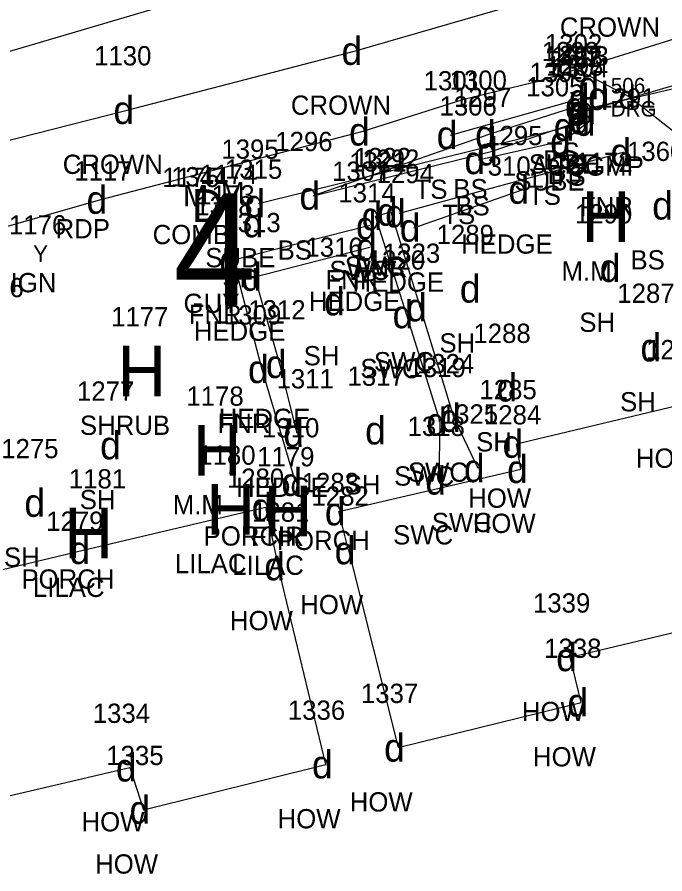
# Model space of a CAD drawing. Extents: x 461160 to 461373, y 202903 to 203086.
# Drawn here: x 461256.86 to 461282.42, y 202914.93 to 202948.72 of the extents above; entities that cross this region are included whole.
import ezdxf

# ---------------------------------------------------------------- set-up
doc = ezdxf.new("R2010")
doc.units = 0
for name, color, linetype in [('Level 11', 7, 'Continuous'), ('Level 12', 7, 'Continuous'), ('Level 13', 7, 'Continuous'), ('Level 14', 7, 'Continuous'), ('Level 15', 7, 'Continuous'), ('Level 43', 7, 'Continuous'), ('Level 46', 7, 'Continuous'), ('Level 47', 7, 'Continuous'), ('Level 48', 7, 'Continuous'), ('Level 49', 7, 'Continuous'), ('Level 59', 7, 'Continuous')]:
    doc.layers.add(name, color=color, linetype=linetype)

msp = doc.modelspace()

# ---------------------------------------------------------------- linework, layer by layer
at = {"layer": 'Level 11'}
msp.add_line((461277.244, 202946.143), (461284.854, 202948.511), dxfattribs=at)
for points in [[(461266.295, 202950.239), (461255.843, 202947.153), (461244.186, 202944.178), (461233.496, 202941.961), (461227.074, 202940.327)], [(461278.937, 202946.67), (461281.047, 202945.559), (461284.301, 202943.008)], [(461277.244, 202946.143), (461274.435, 202945.462), (461270.507, 202944.203)], [(461270.507, 202944.203), (461260.148, 202941.513), (461250.261, 202938.68), (461245.353, 202937.463), (461235.083, 202934.632), (461230.09, 202933.632), (461221.765, 202932.249), (461216.144, 202929.568), (461212.35, 202928.516)]]:
    msp.add_lwpolyline(points, dxfattribs=at)
at = {"layer": 'Level 12'}
for points in [[(461280.82, 202943.388), (461271.934, 202940.975)], [(461273.514, 202930.439), (461273.554, 202932.759), (461272.224, 202936.998), (461271.001, 202940.867), (461271.608, 202941.039), (461272.758, 202937.267), (461274.098, 202932.911), (461275.041, 202930.926)], [(461270.78, 202940.5), (461265.385, 202939.135), (461266.52, 202934.835), (461267.835, 202930.384)]]:
    msp.add_lwpolyline(points, dxfattribs=at)
at = {"layer": 'Level 13'}
for points in [[(461269.939, 202927.688), (461269.552, 202929.221), (461276.743, 202930.893), (461276.564, 202931.887), (461283.181, 202933.463)], [(461278.681, 202923.472), (461285.239, 202925.038), (461283.181, 202933.463)], [(461252.754, 202926.088), (461259.473, 202927.696), (461266.663, 202929.394), (461267.163, 202927.056)], [(461269.939, 202927.688), (461271.89, 202919.907), (461279.12, 202921.685), (461278.681, 202923.472)], [(461252.754, 202926.088), (461254.839, 202917.613), (461261.308, 202919.121), (461261.843, 202917.458), (461269.045, 202919.243), (461267.163, 202927.056)]]:
    msp.add_lwpolyline(points, dxfattribs=at)
at = {"layer": 'Level 14'}
for points in [[(461272.508, 202940.411), (461276.792, 202941.908)], [(461267.913, 202932.314), (461267.227, 202935.033), (461266.245, 202938.474), (461270.784, 202939.649)]]:
    msp.add_lwpolyline(points, dxfattribs=at)
at = {"layer": 'Level 15'}
msp.add_lwpolyline([(461266.383, 202941.371), (461278.58, 202944.397), (461279.146, 202945.068), (461287.08, 202946.903), (461292.543, 202942.281), (461300.755, 202937.586), (461303.654, 202934.874)], dxfattribs=at)
at = {"layer": 'Level 48'}
for points in [[(461211.555, 202934.121), (461222.234, 202936.16), (461232.093, 202938.078), (461241.693, 202939.978), (461251.734, 202942.643), (461261.209, 202945.054), (461270.211, 202947.385), (461280.824, 202950.466), (461289.045, 202954.252), (461296.764, 202959.518)], [(461273.964, 202944.069), (461279.178, 202945.534), (461279.436, 202945.048), (461279.416, 202944.587), (461278.439, 202943.833), (461275.058, 202943.075)], [(461273.964, 202944.069), (461279.178, 202945.534), (461279.436, 202945.048), (461279.416, 202944.587), (461278.439, 202943.833), (461275.058, 202943.075)], [(461268.549, 202941.673), (461275.562, 202943.418), (461279.199, 202944.651), (461279.026, 202945.222), (461275.48, 202944.092), (461268.549, 202941.673)], [(461268.549, 202941.673), (461275.562, 202943.418), (461279.199, 202944.651), (461279.026, 202945.222), (461275.48, 202944.092), (461268.549, 202941.673)]]:
    msp.add_lwpolyline(points, dxfattribs=at)
at = {"layer": 'Level 59'}
msp.add_lwpolyline([(461279.175, 202944.985), (461287.14, 202947.294)], dxfattribs=at)

# ---------------------------------------------------------------- texts
at = {"layer": 'Level 12'}
for p in [(461264.904, 202941.378), (461263.413, 202941.258)]:
    msp.add_text('M', height=0.84, dxfattribs=at).set_placement(p)
at = {"layer": 'Level 14'}
for p in [(461279.128, 202939.848), (461260.816, 202933.761), (461263.787, 202930.63), (461264.319, 202928.304), (461266.582, 202928.24), (461258.717, 202927.369)]:
    msp.add_text('H', height=2, dxfattribs=at).set_placement(p)
at = {"layer": 'Level 15'}
for s, height, p in [('D', 1.3, (461263.747, 202940.634)), ('4', 4.4, (461263.018, 202937.368))]:
    msp.add_text(s, height=height, dxfattribs=at).set_placement(p)
at = {"layer": 'Level 43'}
msp.add_text('Y', height=0.65, dxfattribs=at).set_placement((461257.498, 202939.061))
at = {"layer": 'Level 46'}
for s, height, p in [(' CROWN  ', 0.76, (461277.994, 202947.946)), ('506', 0.609, (461280.287, 202945.711)), (' CROWN  ', 0.76, (461267.381, 202944.865)), ('DRG', 0.609, (461280.283, 202944.798)), (' TS  ', 0.76, (461277.476, 202943.014)), (' CROWN  ', 0.76, (461258.379, 202942.534)), (' 310ACCGMP  ', 0.76, (461275.148, 202942.465)), (' SUBE  ', 0.76, (461276.768, 202942.548)), (' BS  ', 0.76, (461277.336, 202942.702)), (' TS  ', 0.76, (461277.734, 202942.528)), (' BS  ', 0.76, (461277.509, 202942.131)), (' SUBE  ', 0.76, (461276.202, 202941.877)), (' TS  ', 0.76, (461277.714, 202942.067)), (' TS  ', 0.76, (461272.262, 202941.549)), (' BS  ', 0.76, (461273.79, 202941.572)), (' TS  ', 0.76, (461276.737, 202941.313)), (' BS  ', 0.76, (461273.872, 202940.898)), (' FNR  ', 0.76, (461278.786, 202940.868)), (' TS  ', 0.76, (461273.356, 202940.555)), (' RDP  ', 0.76, (461258.096, 202939.993)), (' COMB  ', 0.76, (461261.926, 202939.764)), (' BS  ', 0.76, (461266.859, 202939.153)), (' HEDGE  ', 0.76, (461274.097, 202939.388)), (' SUBE  ', 0.76, (461264.005, 202938.851)), (' BS  ', 0.76, (461280.779, 202938.765)), (' SWC  ', 0.76, (461269.508, 202938.519)), (' FNR  ', 0.76, (461269.9, 202938.455)), (' SH  ', 0.76, (461264.673, 202938.064)), (' SWC  ', 0.76, (461268.901, 202938.347)), (' M.M  ', 0.76, (461278.061, 202938.328)), (' SIGN  ', 0.76, (461255.645, 202937.866)), (' FNR  ', 0.76, (461268.746, 202937.98)), (' HEDGE  ', 0.76, (461269.813, 202937.891)), (' GUY  ', 0.76, (461263.145, 202937.048)), (' HEDGE  ', 0.76, (461268.089, 202937.129)), (' FNR  ', 0.76, (461263.351, 202936.615)), (' SH  ', 0.76, (461278.76, 202936.303)), (' HEDGE  ', 0.76, (461263.55, 202935.954)), (' SH  ', 0.76, (461273.243, 202935.488)), (' SH  ', 0.76, (461267.886, 202934.984)), (' SWC  ', 0.76, (461270.658, 202934.747)), (' SWC  ', 0.76, (461270.124, 202934.478)), (' SH  ', 0.76, (461280.369, 202933.168)), (' HEDGE  ', 0.76, (461264.532, 202932.513)), (' SHRUB  ', 0.76, (461259.058, 202932.241)), (' FNR  ', 0.76, (461264.486, 202932.315)), (' SH  ', 0.76, (461274.691, 202931.588)), (' HOW  ', 0.76, (461280.994, 202930.943)), (' SWC  ', 0.76, (461271.998, 202930.391)), (' SWC  ', 0.76, (461271.454, 202930.239)), (' HEDGE  ', 0.76, (461265.218, 202929.794)), (' SH  ', 0.76, (461269.506, 202929.896)), (' SH  ', 0.76, (461259.05, 202929.31)), (' HOW  ', 0.76, (461274.377, 202929.367)), (' M.M  ', 0.76, (461262.72, 202929.11)), (' SWC  ', 0.76, (461272.941, 202928.406)), (' HOW  ', 0.76, (461274.556, 202928.373)), (' SWC  ', 0.76, (461271.414, 202927.919)), (' PORCH  ', 0.76, (461263.938, 202927.874)), (' FNR  ', 0.76, (461265.801, 202927.864)), (' PORCH  ', 0.76, (461266.827, 202927.701)), (' SH  ', 0.76, (461256.06, 202927.04)), (' LILAC  ', 0.76, (461262.806, 202926.784)), (' LILAC  ', 0.76, (461265.069, 202926.72)), (' PORCH  ', 0.76, (461256.748, 202926.176)), (' LILAC  ', 0.76, (461257.204, 202925.849)), (' HOW  ', 0.76, (461267.752, 202925.168)), (' HOW  ', 0.76, (461264.976, 202924.536)), (' HOW  ', 0.76, (461276.494, 202920.952)), (' HOW  ', 0.76, (461276.933, 202919.165)), (' HOW  ', 0.76, (461269.703, 202917.387)), (' HOW  ', 0.76, (461259.121, 202916.601)), (' HOW  ', 0.76, (461266.858, 202916.723)), (' HOW  ', 0.76, (461259.656, 202914.938))]:
    msp.add_text(s, height=height, dxfattribs=at).set_placement(p)
at = {"layer": 'Level 47'}
for height, p in [(1.1, (461269.661, 202946.835)), (1.1, (461279.004, 202945.473)), (1.1, (461278.628, 202944.984)), (1.1, (461279.39, 202945.054)), (0.914, (461280.59, 202945.102)), (1.1, (461260.659, 202944.504)), (1.1, (461278.476, 202944.672)), (1.1, (461278.596, 202944.518)), (1.1, (461278.625, 202944.435)), (1.1, (461278.886, 202944.498)), (1.1, (461278.649, 202944.101)), (1.1, (461278.03, 202943.847)), (1.1, (461278.866, 202944.037)), (1.1, (461269.957, 202943.653)), (1.1, (461273.414, 202943.519)), (1.1, (461274.93, 202943.542)), (1.1, (461277.889, 202943.283)), (1.1, (461275.012, 202942.868)), (1.1, (461280.27, 202942.838)), (1.1, (461274.508, 202942.525)), (1.1, (461267.999, 202941.123)), (1.1, (461276.242, 202941.358)), (1.1, (461259.598, 202940.963)), (1.1, (461265.833, 202940.821)), (1.1, (461281.919, 202940.735)), (1.1, (461271.058, 202940.489)), (1.1, (461271.384, 202940.425)), (1.1, (461265.759, 202940.034)), (1.1, (461270.451, 202940.317)), (1.1, (461270.23, 202939.95)), (1.1, (461271.958, 202939.861)), (1.1, (461270.234, 202939.099)), (1.1, (461264.835, 202938.585)), (1.1, (461279.846, 202938.273)), (1.1, (461265.695, 202937.924)), (1.1, (461274.329, 202937.458)), (1.1, (461268.972, 202936.954)), (1.1, (461272.208, 202936.717)), (1.1, (461271.674, 202936.448)), (1.1, (461281.455, 202935.138)), (1.1, (461266.677, 202934.483)), (1.1, (461265.97, 202934.285)), (1.1, (461275.777, 202933.558)), (1.1, (461273.548, 202932.361)), (1.1, (461273.004, 202932.209)), (1.1, (461267.363, 202931.764)), (1.1, (461270.592, 202931.866)), (1.1, (461260.136, 202931.28)), (1.1, (461276.014, 202931.337)), (1.1, (461274.491, 202930.376)), (1.1, (461276.193, 202930.343)), (1.1, (461267.285, 202929.834)), (1.1, (461272.964, 202929.889)), (1.1, (461257.146, 202929.01)), (1.1, (461266.113, 202928.844)), (1.1, (461269.002, 202928.671)), (1.1, (461258.923, 202927.146)), (1.1, (461269.389, 202927.138)), (1.1, (461266.613, 202926.506)), (1.1, (461278.131, 202922.922)), (1.1, (461278.57, 202921.135)), (1.1, (461271.34, 202919.357)), (1.1, (461260.758, 202918.571)), (1.1, (461268.495, 202918.693)), (1.1, (461261.293, 202916.908))]:
    msp.add_text('d', height=height, dxfattribs=at).set_placement(p)
at = {"layer": 'Level 49'}
for s, p in [(' 1302 ', (461277.404, 202947.294)), (' 1299 ', (461277.279, 202946.982)), (' 1130 ', (461259.618, 202946.814)), (' 1402 ', (461277.401, 202946.745)), (' 1397 ', (461277.402, 202946.828)), (' 1303 ', (461277.662, 202946.808)), (' 1298 ', (461277.455, 202946.411)), (' 1304 ', (461277.642, 202946.347)), (' 1301 ', (461272.621, 202945.829)), (' 1300 ', (461273.643, 202945.852)), (' 1396 ', (461276.797, 202946.157)), (' 1305 ', (461276.665, 202945.593)), (' 1297 ', (461273.818, 202945.178)), (' 1306 ', (461273.245, 202944.835)), (' 1291 ', (461279.507, 202945.148)), (' 1295 ', (461275.048, 202943.668)), (' 1395 ', (461264.639, 202943.131)), (' 1296 ', (461266.766, 202943.433)), (' 1322 ', (461269.864, 202942.799)), (' 1360 ', (461280.644, 202943.045)), (' 1321 ', (461269.688, 202942.627)), (' 1292 ', (461270.19, 202942.735)), (' 1172 ', (461278.6, 202942.608)), (' 1117 ', (461258.835, 202942.273)), (' 1174 ', (461263.796, 202942.138)), (' 1315 ', (461264.781, 202942.344)), (' 1307 ', (461269.006, 202942.26)), (' 1294 ', (461270.764, 202942.171)), (' 1175 ', (461262.305, 202942.018)), (' 1344 ', (461262.653, 202942.044)), (' 1173 ', (461263.69, 202941.328)), (' 1314 ', (461269.256, 202941.409)), (' 1308 ', (461263.611, 202940.895)), (' 1290 ', (461278.589, 202940.583)), (' 1176 ', (461256.256, 202940.146)), (' 1313 ', (461264.717, 202940.234)), (' 1289 ', (461273.132, 202939.768)), (' 1316 ', (461267.955, 202939.264)), (' 1320 ', (461270.417, 202938.758)), (' 1323 ', (461271.014, 202939.027)), (' 1276 ', (461254.58, 202937.671)), (' 1287 ', (461280.261, 202937.448)), (' 1312 ', (461265.699, 202936.793)), (' 1177 ', (461260.288, 202936.521)), (' 1309 ', (461264.743, 202936.595)), (' 1288 ', (461274.583, 202935.868)), (' 1286 ', (461281.398, 202935.223)), (' 1319 ', (461272.023, 202934.519)), (' 1324 ', (461272.354, 202934.671)), (' 1311 ', (461266.815, 202934.074)), (' 1317 ', (461269.614, 202934.176)), (' 1277 ', (461258.942, 202933.59)), (' 1178 ', (461263.259, 202933.39)), (' 1285 ', (461274.82, 202933.647)), (' 1325 ', (461273.297, 202932.686)), (' 1284 ', (461274.999, 202932.653)), (' 1310 ', (461266.244, 202932.144)), (' 1318 ', (461271.986, 202932.199)), (' 1275 ', (461255.952, 202931.32)), (' 1180 ', (461263.728, 202931.064)), (' 1179 ', (461266.051, 202931)), (' 1181 ', (461258.619, 202930.129)), (' 1280 ', (461264.856, 202930.154)), (' 1283 ', (461267.808, 202929.981)), (' 1282 ', (461268.195, 202929.448)), (' 1281 ', (461265.85, 202928.816)), (' 1279 ', (461257.726, 202928.456)), (' 1339 ', (461276.934, 202925.232)), (' 1338 ', (461277.376, 202923.445)), (' 1337 ', (461270.146, 202921.667)), (' 1334 ', (461259.564, 202920.881)), (' 1336 ', (461267.262, 202921.003)), (' 1335 ', (461260.099, 202919.218))]:
    msp.add_text(s, height=0.76, dxfattribs=at).set_placement(p)

doc.saveas('drawing.dxf')
